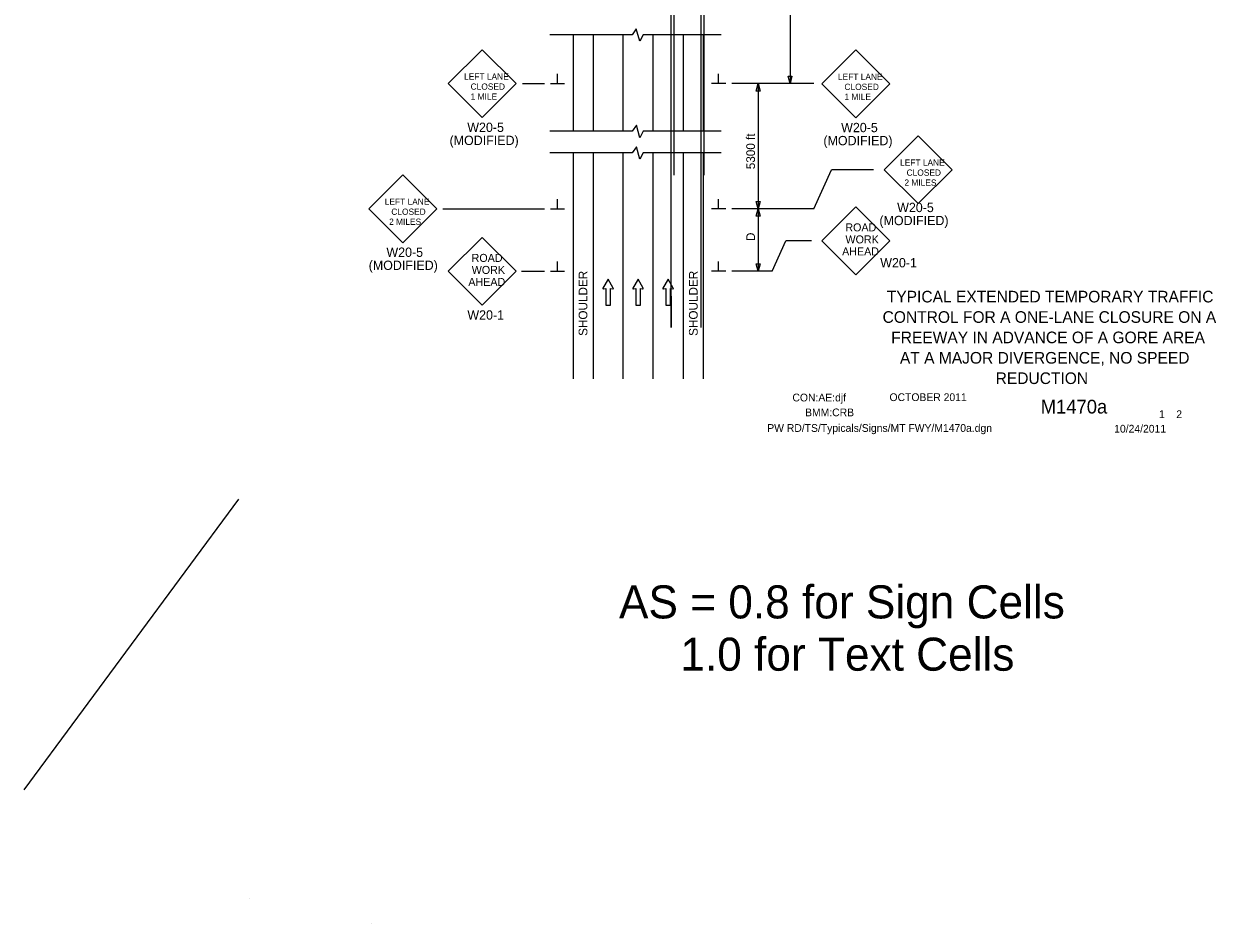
# Model space of a CAD drawing. Extents: x 16476 to 18475, y 6827 to 8243.
# Drawn here: x 16476 to 17429, y 6827 to 7546 of the extents above; entities that cross this region are included whole.
import ezdxf

# ---------------------------------------------------------------- set-up
doc = ezdxf.new("R2010")
doc.units = 0
for name, color, linetype in [('ALI_LEGAL_EX', 7, 'Continuous'), ('BORDER', 7, 'Continuous'), ('BORDER_SIGNAL_WO', 7, 'Continuous'), ('MT_SCRATCH_LEVEL_E', 7, 'Continuous'), ('PAVT_EDGE_EX', 7, 'Continuous'), ('TRAFFIC_SIGNS_PR', 7, 'Continuous'), ('TYPICAL_TEXT_DIMEN_PR', 7, 'Continuous')]:
    doc.layers.add(name, color=color, linetype=linetype)

msp = doc.modelspace()

# ---------------------------------------------------------------- linework, layer by layer
at = {"layer": 'ALI_LEGAL_EX'}
for p, q in [((16995.95, 8243.16), (16995.95, 7425.02)), ((17019.95, 8243.16), (17019.95, 7425.02)), ((16993.65, 7303.41), (16993.65, 7803.75)), ((17017.65, 7303.41), (17017.65, 7803.75)), ((16955.32, 7460.22), (16955.32, 7537.37)), ((16979.32, 7460.22), (16979.32, 7537.37)), ((16955.32, 7262.27), (16955.32, 7443.08)), ((16979.32, 7262.27), (16979.32, 7443.08))]:
    msp.add_line(p, q, dxfattribs=at)
for points in [[(16955.32, 7460.22), (16955.32, 7485.22)], [(16979.32, 7460.22), (16979.32, 7485.22)], [(16955.32, 7362.27), (16955.32, 7387.27)], [(16979.32, 7362.27), (16979.32, 7387.27)], [(16993.65, 7328.41), (16993.65, 7303.41)], [(16955.32, 7262.27), (16955.32, 7287.27)], [(16979.32, 7262.27), (16979.32, 7287.27)]]:
    msp.add_lwpolyline(points, dxfattribs=at)
at = {"layer": 'MT_SCRATCH_LEVEL_E'}
for p, q in [((16943.31, 7342.15), (16939.2, 7334.91)), ((16947.46, 7334.91), (16943.31, 7342.15)), ((16967.22, 7342.15), (16963.11, 7334.91)), ((16971.37, 7334.91), (16967.22, 7342.15)), ((16991.27, 7342.15), (16987.16, 7334.91)), ((16995.42, 7334.91), (16991.27, 7342.15)), ((16939.69, 7334.22), (16941.46, 7334.54)), ((16941.46, 7334.54), (16941.46, 7321.28)), ((16945.21, 7321.28), (16945.21, 7334.54)), ((16945.21, 7334.54), (16946.98, 7334.22)), ((16963.59, 7334.22), (16965.37, 7334.54)), ((16965.37, 7334.54), (16965.37, 7321.28)), ((16969.11, 7321.28), (16969.11, 7334.54)), ((16969.11, 7334.54), (16970.89, 7334.22)), ((16987.64, 7334.22), (16989.42, 7334.54)), ((16989.42, 7334.54), (16989.42, 7321.28)), ((16993.16, 7321.28), (16993.16, 7334.54)), ((16993.16, 7334.54), (16994.94, 7334.22)), ((16941.46, 7321.28), (16945.21, 7321.28)), ((16965.37, 7321.28), (16969.11, 7321.28)), ((16989.42, 7321.28), (16993.16, 7321.28))]:
    msp.add_line(p, q, dxfattribs=at)
for centre, start, end in [((16939.61, 7334.68), 150.42484, 279.96381), ((16947.05, 7334.68), 260.03619, 29.77312), ((16963.52, 7334.68), 150.42484, 279.96381), ((16970.96, 7334.68), 260.03619, 29.77312), ((16987.57, 7334.68), 150.42484, 279.96381), ((16995.01, 7334.68), 260.03619, 29.77312)]:
    msp.add_arc(centre, 0.463, start, end, dxfattribs=at)
at = {"layer": 'PAVT_EDGE_EX'}
for p, q in [((16915.32, 7537.37), (16915.32, 7460.23)), ((16931.32, 7537.37), (16931.32, 7460.23)), ((17003.32, 7537.39), (17003.32, 7460.23)), ((17019.32, 7537.39), (17019.32, 7460.23)), ((16915.32, 7443.09), (16915.32, 7262.27)), ((16931.32, 7443.09), (16931.32, 7262.27)), ((17003.32, 7443.09), (17003.32, 7262.27)), ((17019.32, 7443.09), (17019.32, 7262.27))]:
    msp.add_line(p, q, dxfattribs=at)
at = {"layer": 'TRAFFIC_SIGNS_PR'}
for p, q in [((16842.55, 7525.43), (16815.4, 7498.28)), ((16869.71, 7498.28), (16842.55, 7525.43)), ((17141.45, 7525.25), (17114.3, 7498.09)), ((17168.61, 7498.09), (17141.45, 7525.25)), ((16815.4, 7498.28), (16842.55, 7471.12)), ((16842.55, 7471.12), (16869.71, 7498.28)), ((17114.3, 7498.09), (17141.45, 7470.94)), ((17141.45, 7470.94), (17168.61, 7498.09)), ((17191.13, 7456.69), (17163.98, 7429.53)), ((17218.29, 7429.53), (17191.13, 7456.69)), ((17163.98, 7429.53), (17191.13, 7402.38)), ((17191.13, 7402.38), (17218.29, 7429.53)), ((16779.13, 7425.45), (16751.97, 7398.29)), ((16806.28, 7398.29), (16779.13, 7425.45)), ((16751.97, 7398.29), (16779.13, 7371.13)), ((16779.13, 7371.13), (16806.28, 7398.29)), ((17141.45, 7399.82), (17114.3, 7372.66)), ((17168.61, 7372.66), (17141.45, 7399.82)), ((16842.63, 7375.43), (16815.47, 7348.28)), ((16869.78, 7348.28), (16842.63, 7375.43)), ((17114.3, 7372.66), (17141.45, 7345.51)), ((17141.45, 7345.51), (17168.61, 7372.66)), ((16815.47, 7348.28), (16842.63, 7321.12)), ((16842.63, 7321.12), (16869.78, 7348.28))]:
    msp.add_line(p, q, dxfattribs=at)
at = {"layer": 'TYPICAL_TEXT_DIMEN_PR'}
for p, q in [((17088.75, 7798.28), (17088.75, 7498.28)), ((16965.83, 7542.17), (16962.57, 7537.37)), ((16968.57, 7532.23), (16965.83, 7542.17)), ((16962.57, 7537.37), (16896.63, 7537.37)), ((16971.31, 7537.37), (16968.57, 7532.23)), ((17033.65, 7537.37), (16971.31, 7537.37)), ((16902.94, 7498.28), (16902.94, 7506.06)), ((17031.69, 7498.28), (17031.69, 7506.06)), ((17088.75, 7498.28), (17087.18, 7504.14)), ((17087.18, 7504.14), (17088.75, 7504.14)), ((17088.75, 7504.14), (17090.32, 7504.14)), ((17090.32, 7504.14), (17088.75, 7498.28)), ((16874.95, 7498.28), (16892.32, 7498.28)), ((16897.32, 7498.28), (16908.57, 7498.28)), ((17037.32, 7498.28), (17026.07, 7498.28)), ((17107.79, 7498.28), (17042.32, 7498.28)), ((17061.74, 7492.41), (17063.32, 7498.28)), ((17063.32, 7498.28), (17063.32, 7398.28)), ((17063.32, 7498.28), (17064.89, 7492.41)), ((17063.32, 7492.41), (17061.74, 7492.41)), ((17064.89, 7492.41), (17063.32, 7492.41)), ((16965.92, 7465.02), (16962.66, 7460.22)), ((16968.66, 7455.08), (16965.92, 7465.02)), ((16962.66, 7460.22), (16896.72, 7460.22)), ((16971.4, 7460.22), (16968.66, 7455.08)), ((17033.74, 7460.22), (16971.4, 7460.22)), ((16965.92, 7447.88), (16962.66, 7443.08)), ((16968.66, 7437.94), (16965.92, 7447.88)), ((16962.66, 7443.08), (16896.72, 7443.08)), ((16971.4, 7443.08), (16968.66, 7437.94)), ((17033.74, 7443.08), (16971.4, 7443.08)), ((17107.7, 7398.28), (17121.94, 7429.53)), ((17155.57, 7429.53), (17121.94, 7429.53)), ((16811.06, 7398.28), (16892.32, 7398.28)), ((16897.32, 7398.28), (16908.57, 7398.28)), ((16902.94, 7398.28), (16902.94, 7406.06)), ((17037.32, 7398.28), (17026.07, 7398.28)), ((17031.69, 7398.28), (17031.69, 7406.06)), ((17107.7, 7398.28), (17042.32, 7398.28)), ((17063.32, 7398.28), (17061.74, 7404.14)), ((17061.74, 7404.14), (17063.32, 7404.14)), ((17061.74, 7392.41), (17063.32, 7398.28)), ((17063.32, 7404.14), (17064.89, 7404.14)), ((17064.89, 7404.14), (17063.32, 7398.28)), ((17063.32, 7398.28), (17063.32, 7348.28)), ((17063.32, 7398.28), (17064.89, 7392.41)), ((17063.32, 7392.41), (17061.74, 7392.41)), ((17064.89, 7392.41), (17063.32, 7392.41)), ((17074.36, 7348.28), (17085.47, 7372.66)), ((17105.89, 7372.66), (17085.47, 7372.66)), ((16902.94, 7348.28), (16902.94, 7356.06)), ((17031.69, 7348.28), (17031.69, 7356.06)), ((17063.32, 7348.28), (17061.74, 7354.14)), ((17061.74, 7354.14), (17063.32, 7354.14)), ((17063.32, 7354.14), (17064.89, 7354.14)), ((17064.89, 7354.14), (17063.32, 7348.28)), ((16874.06, 7348.28), (16892.32, 7348.28)), ((16897.32, 7348.28), (16908.57, 7348.28)), ((17037.32, 7348.28), (17026.07, 7348.28)), ((17074.36, 7348.28), (17042.32, 7348.28)), ((16647.75, 7166.25), (16476.17, 6933.89)), ((16656.86, 6847.34), (16656.84, 6847.33)), ((16753.81, 6827.31), (16753.81, 6827.31))]:
    msp.add_line(p, q, dxfattribs=at)

# ---------------------------------------------------------------- texts
at = {"layer": 'BORDER'}
for s, p in [('TYPICAL EXTENDED TEMPORARY TRAFFIC', (17166.14, 7323.41)), ('CONTROL FOR A ONE-LANE CLOSURE ON A', (17162.76, 7307.11)), ('FREEWAY IN ADVANCE OF A GORE AREA', (17169.65, 7290.81)), ('AT A MAJOR DIVERGENCE, NO SPEED', (17176.64, 7274.51)), ('REDUCTION', (17253.15, 7258.21))]:
    msp.add_text(s, height=9.3, dxfattribs=at).set_placement(p)
at = {"layer": 'BORDER_SIGNAL_WO'}
for s, height, p in [('CON:AE:djf  ', 6.2, (17090.69, 7244.31)), ('    OCTOBER 2011    ', 6.2, (17159.08, 7244.59)), ('    M1470a   ', 11, (17272.86, 7234.63)), ('BMM:CRB   ', 6.2, (17100.81, 7232.42)), (' 1    2 ', 6.2, (17381.45, 7230.95)), ('PW RD/TS/Typicals/Signs/MT FWY/M1470a.dgn      ', 6.2, (17070.55, 7219.96)), ('10/24/2011    ', 6.2, (17347.93, 7219.38)), ('AS = 0.8 for Sign Cells', 26.4241, (16952.01, 7070.86)), ('     1.0 for Text Cells', 26.4241, (16952.01, 7029.07))]:
    msp.add_text(s, height=height, dxfattribs=at).set_placement(p)
at = {"layer": 'TRAFFIC_SIGNS_PR'}
for s, height, p in [('LEFT LANE', 5.001, (16828.18, 7501.43)), ('LEFT LANE', 5.001, (17127.08, 7501.24)), ('CLOSED', 5.001, (16833.38, 7493.43)), ('CLOSED', 5.001, (17132.29, 7493.24)), ('1 MILE', 5.001, (16833.38, 7485.43)), ('1 MILE', 5.001, (17132.28, 7485.24)), ('W20-5', 7.441, (16830.72, 7459.68)), ('W20-5', 7.441, (17129.63, 7459.5)), ('(MODIFIED)', 7.441, (16816.54, 7449.24)), ('(MODIFIED)', 7.441, (17115.44, 7449.06)), ('LEFT LANE', 5.001, (17176.76, 7432.68)), ('CLOSED', 5.001, (17181.97, 7424.68)), ('2 MILES', 5.001, (17180.22, 7416.68)), ('LEFT LANE', 5.001, (16764.75, 7401.44)), ('CLOSED', 5.001, (16769.96, 7393.44)), ('W20-5', 7.441, (17174.4, 7395.62)), ('2 MILES', 5.001, (16768.21, 7385.44)), ('(MODIFIED)', 7.441, (17160.22, 7385.18)), ('ROAD', 6.401, (17132.99, 7380.2)), ('WORK', 6.401, (17133.1, 7370.6)), ('W20-5', 7.441, (16766.06, 7359.84)), ('ROAD', 6.401, (16834.17, 7355.81)), ('AHEAD', 6.401, (17130.41, 7361)), ('(MODIFIED)', 7.441, (16751.88, 7349.4)), ('WORK', 6.401, (16834.27, 7346.21)), ('W20-1', 7.441, (17160.88, 7351.43)), ('AHEAD', 6.401, (16831.58, 7336.61)), ('W20-1', 7.441, (16830.79, 7309.68))]:
    msp.add_text(s, height=height, dxfattribs=at).set_placement(p)
at = {"layer": 'TYPICAL_TEXT_DIMEN_PR'}
for s, p in [('5300 ft', (17060.76, 7429.88)), ('D', (17060.76, 7372.5)), ('SHOULDER', (16926.74, 7296.69)), ('SHOULDER', (17014.94, 7296.69))]:
    msp.add_text(s, height=7, rotation=90, dxfattribs=at).set_placement(p)

doc.saveas('drawing.dxf')
